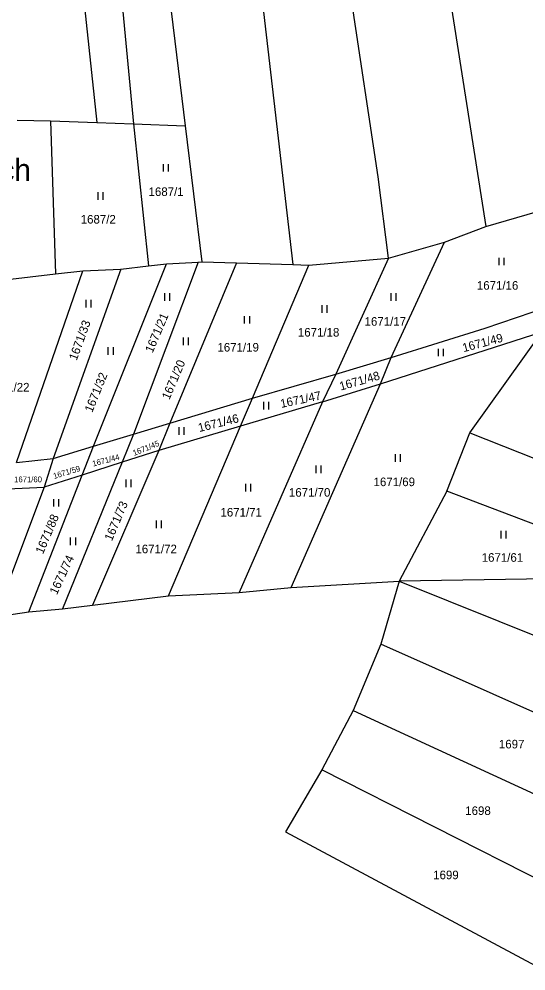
# Model space of a CAD drawing. Extents: x -820420 to -815896, y -1105820 to -1103643.
# Drawn here: x -818858.6 to -818758.1, y -1105776.2 to -1105587.5 of the extents above; entities that cross this region are included whole.
import ezdxf
from ezdxf.enums import TextEntityAlignment as Align

# ---------------------------------------------------------------- set-up
doc = ezdxf.new("R2010")
doc.units = 0
doc.header["$LTSCALE"] = 0.68
for name, color, linetype, lineweight in [('1', 7, 'Continuous', 25), ('3', 7, 'Continuous', 25), ('7', 7, 'Continuous', 13)]:
    doc.layers.add(name, color=color, linetype=linetype, lineweight=lineweight)
doc.layers.add('2', color=7, linetype='Continuous')

msp = doc.modelspace()

# ---------------------------------------------------------------- linework, layer by layer
at = {"layer": '1'}
for p, q in [((-818788.31, -1105486.7), (-818766.07, -1105628.64)), ((-818821.17, -1105491.56), (-818804.3, -1105636.15)), ((-818851.26, -1105531.39), (-818843.19, -1105608.05)), ((-818843.21, -1105531.89), (-818835.93, -1105608.31)), ((-818834.93, -1105532.61), (-818825.68, -1105608.67)), ((-818787.42, -1105618.77), (-818797.13, -1105553.87)), ((-818858.99, -1105607.58), (-818852.36, -1105607.72)), ((-818852.36, -1105607.72), (-818843.19, -1105608.05)), ((-818852.36, -1105607.72), (-818851.38, -1105638.05)), ((-818843.19, -1105608.05), (-818835.93, -1105608.31)), ((-818835.93, -1105608.31), (-818832.96, -1105636.44)), ((-818835.93, -1105608.31), (-818825.68, -1105608.67)), ((-818825.68, -1105608.67), (-818822.37, -1105635.67)), ((-818785.34, -1105634.91), (-818787.42, -1105618.77)), ((-818766.07, -1105628.64), (-818749.42, -1105623.81)), ((-818774.23, -1105631.72), (-818766.07, -1105628.64)), ((-818785.34, -1105634.91), (-818774.23, -1105631.72)), ((-818784.86, -1105654.62), (-818774.23, -1105631.72)), ((-818801.16, -1105636.33), (-818785.34, -1105634.91)), ((-818785.34, -1105634.91), (-818795.81, -1105657.93)), ((-818838.43, -1105637.08), (-818851.81, -1105674.65)), ((-818845.98, -1105637.45), (-818838.43, -1105637.08)), ((-818843.83, -1105672.19), (-818829.35, -1105636.05)), ((-818838.43, -1105637.08), (-818832.96, -1105636.44)), ((-818823.07, -1105635.74), (-818835.89, -1105669.82)), ((-818832.96, -1105636.44), (-818829.35, -1105636.05)), ((-818829.35, -1105636.05), (-818823.07, -1105635.74)), ((-818815.5, -1105635.86), (-818828.73, -1105667.61)), ((-818823.07, -1105635.74), (-818822.37, -1105635.67)), ((-818822.37, -1105635.67), (-818815.5, -1105635.86)), ((-818815.5, -1105635.86), (-818804.3, -1105636.15)), ((-818812.33, -1105662.65), (-818801.16, -1105636.33)), ((-818804.3, -1105636.15), (-818801.16, -1105636.33)), ((-818861.39, -1105639.19), (-818851.38, -1105638.05)), ((-818859.12, -1105675.46), (-818845.98, -1105637.45)), ((-818851.38, -1105638.05), (-818845.98, -1105637.45)), ((-818766.17, -1105648.82), (-818751.84, -1105643.87)), ((-818786.95, -1105659.82), (-818754.88, -1105649.51)), ((-818784.86, -1105654.62), (-818766.17, -1105648.82)), ((-818769.23, -1105669.54), (-818754.88, -1105649.51)), ((-818795.81, -1105657.93), (-818784.86, -1105654.62)), ((-818786.95, -1105659.82), (-818784.86, -1105654.62)), ((-818812.33, -1105662.65), (-818795.81, -1105657.93)), ((-818795.81, -1105657.93), (-818798.43, -1105663.39)), ((-818804.66, -1105700.2), (-818786.95, -1105659.82)), ((-818798.43, -1105663.39), (-818786.95, -1105659.82)), ((-818828.73, -1105667.61), (-818812.33, -1105662.65)), ((-818798.43, -1105663.39), (-818814.95, -1105701.17)), ((-818814.71, -1105668.21), (-818812.33, -1105662.65)), ((-818798.43, -1105663.39), (-818814.71, -1105668.21)), ((-818835.89, -1105669.82), (-818828.73, -1105667.61)), ((-818828.73, -1105667.61), (-818830.91, -1105673.08)), ((-818814.71, -1105668.21), (-818830.91, -1105673.08)), ((-818829, -1105701.85), (-818814.71, -1105668.21)), ((-818843.83, -1105672.19), (-818835.89, -1105669.82)), ((-818835.89, -1105669.82), (-818838.16, -1105675.39)), ((-818851.81, -1105674.65), (-818843.83, -1105672.19)), ((-818846.06, -1105677.91), (-818843.83, -1105672.19)), ((-818830.91, -1105673.08), (-818844.05, -1105703.73)), ((-818830.91, -1105673.08), (-818838.16, -1105675.39)), ((-818859.12, -1105675.46), (-818851.81, -1105674.65)), ((-818851.81, -1105674.65), (-818853.62, -1105680.32)), ((-818838.16, -1105675.39), (-818849.98, -1105704.43)), ((-818838.16, -1105675.39), (-818846.06, -1105677.91)), ((-818856.63, -1105705.05), (-818846.06, -1105677.91)), ((-818846.06, -1105677.91), (-818853.62, -1105680.32)), ((-818853.62, -1105680.32), (-818863.3, -1105706)), ((-818860.91, -1105680.64), (-818853.62, -1105680.32)), ((-818773.82, -1105681.11), (-818783.23, -1105698.96)), ((-818728.85, -1105698.12), (-818773.82, -1105681.11)), ((-818804.66, -1105700.2), (-818783.23, -1105698.96)), ((-818783.23, -1105698.96), (-818786.91, -1105711.43)), ((-818728.85, -1105698.12), (-818783.23, -1105698.96)), ((-818783.23, -1105698.96), (-818725.43, -1105722.12)), ((-818829, -1105701.85), (-818814.95, -1105701.17)), ((-818814.95, -1105701.17), (-818804.66, -1105700.2)), ((-818844.05, -1105703.73), (-818829, -1105701.85)), ((-818863.3, -1105706), (-818856.63, -1105705.05)), ((-818856.63, -1105705.05), (-818849.98, -1105704.43)), ((-818849.98, -1105704.43), (-818844.05, -1105703.73)), ((-818786.91, -1105711.43), (-818792.36, -1105724.6)), ((-818731.23, -1105736.23), (-818786.91, -1105711.43)), ((-818792.36, -1105724.6), (-818798.58, -1105736.34)), ((-818792.36, -1105724.6), (-818740.08, -1105748.69)), ((-818798.58, -1105736.34), (-818805.75, -1105748.63)), ((-818747.45, -1105762.29), (-818798.58, -1105736.34)), ((-818805.75, -1105748.63), (-818754.28, -1105776.22))]:
    msp.add_line(p, q, dxfattribs=at)
msp.add_lwpolyline([(-818773.82, -1105681.11), (-818769.23, -1105669.54), (-818712.97, -1105691.83)], dxfattribs=at)
at = {"layer": '3'}
for p, q in [((-818829.961, -1105617.76), (-818829.961, -1105616.26)), ((-818828.96, -1105617.76), (-818828.96, -1105616.26)), ((-818842.931, -1105623.36), (-818842.931, -1105621.86)), ((-818841.93, -1105623.36), (-818841.93, -1105621.86)), ((-818763.411, -1105636.34), (-818763.411, -1105634.84)), ((-818762.41, -1105636.34), (-818762.41, -1105634.84)), ((-818829.721, -1105643.37), (-818829.721, -1105641.87)), ((-818828.72, -1105643.37), (-818828.72, -1105641.87)), ((-818784.831, -1105643.37), (-818784.831, -1105641.87)), ((-818783.83, -1105643.37), (-818783.83, -1105641.87)), ((-818845.311, -1105644.68), (-818845.311, -1105643.18)), ((-818844.31, -1105644.68), (-818844.31, -1105643.18)), ((-818798.531, -1105645.75), (-818798.531, -1105644.25)), ((-818797.53, -1105645.75), (-818797.53, -1105644.25)), ((-818813.881, -1105647.89), (-818813.881, -1105646.39)), ((-818812.88, -1105647.89), (-818812.88, -1105646.39)), ((-818826.031, -1105652.18), (-818826.031, -1105650.68)), ((-818825.03, -1105652.18), (-818825.03, -1105650.68)), ((-818840.911, -1105654.08), (-818840.911, -1105652.58)), ((-818839.91, -1105654.08), (-818839.91, -1105652.58)), ((-818775.431, -1105654.38), (-818775.431, -1105652.88)), ((-818774.43, -1105654.38), (-818774.43, -1105652.88)), ((-818810.071, -1105664.92), (-818810.071, -1105663.42)), ((-818809.07, -1105664.92), (-818809.07, -1105663.42)), ((-818826.861, -1105669.92), (-818826.861, -1105668.42)), ((-818825.86, -1105669.92), (-818825.86, -1105668.42)), ((-818784.001, -1105675.28), (-818784.001, -1105673.78)), ((-818783, -1105675.28), (-818783, -1105673.78)), ((-818799.721, -1105677.55), (-818799.721, -1105676.05)), ((-818798.72, -1105677.55), (-818798.72, -1105676.05)), ((-818837.381, -1105680.31), (-818837.381, -1105678.81)), ((-818836.38, -1105680.31), (-818836.38, -1105678.81)), ((-818813.651, -1105681.18), (-818813.651, -1105679.68)), ((-818812.65, -1105681.18), (-818812.65, -1105679.68)), ((-818851.731, -1105684.17), (-818851.731, -1105682.67)), ((-818850.73, -1105684.17), (-818850.73, -1105682.67)), ((-818831.341, -1105688.43), (-818831.341, -1105686.93)), ((-818830.34, -1105688.43), (-818830.34, -1105686.93)), ((-818763.051, -1105690.47), (-818763.051, -1105688.97)), ((-818762.05, -1105690.47), (-818762.05, -1105688.97)), ((-818848.371, -1105691.8), (-818848.371, -1105690.3)), ((-818847.37, -1105691.8), (-818847.37, -1105690.3))]:
    msp.add_line(p, q, dxfattribs=at)

# ---------------------------------------------------------------- texts
at = {"layer": '2'}
for s, height, p in [('1687/1', 1.7, (-818829.45, -1105622.595)), ('1687/2', 1.7, (-818842.9, -1105628.065)), ('1671/16', 1.7, (-818763.729, -1105641.175)), ('1671/17', 1.7, (-818785.989, -1105648.315)), ('1671/18', 1.7, (-818799.209, -1105650.465)), ('1671/19', 1.7, (-818815.159, -1105653.435)), ('1671/22', 1.7, (-818860.639, -1105661.355)), ('1671/60', 1.14, (-818856.82, -1105679.345)), ('1671/69', 1.7, (-818784.209, -1105680.115)), ('1671/70', 1.7, (-818800.989, -1105682.205)), ('1671/71', 1.7, (-818814.559, -1105686.135)), ('1671/72', 1.7, (-818831.419, -1105693.415)), ('1671/61', 1.7, (-818762.769, -1105695.105)), ('1697', 1.7, (-818760.94, -1105732.105)), ('1698', 1.7, (-818767.61, -1105745.295)), ('1699', 1.7, (-818773.97, -1105758.035))]:
    msp.add_text(s, height=height, dxfattribs=at).set_placement(p, align=Align.CENTER)
for s, height, rotation, p in [('1671/21', 1.7, 67, (-818830.5266, -1105650.0371)), ('1671/33', 1.7, 70, (-818845.7759, -1105651.4572)), ('1671/49', 1.7, 15, (-818766.488, -1105652.4997)), ('1671/20', 1.7, 67, (-818827.1966, -1105659.3271)), ('1671/32', 1.7, 68, (-818842.5598, -1105661.8264)), ('1671/48', 1.7, 16, (-818790.8728, -1105660.0536)), ('1671/47', 1.7, 12, (-818802.6007, -1105663.7661)), ('1671/46', 1.7, 14, (-818818.8821, -1105668.4058)), ('1671/45', 1.14, 22, (-818833.224, -1105673.0999)), ('1671/44', 1.14, 15, (-818841.2405, -1105675.5349)), ('1671/59', 1.139, 17, (-818849.0015, -1105677.8956)), ('1671/73', 1.7, 67, (-818838.5866, -1105687.3371)), ('1671/88', 1.7, 67, (-818852.2466, -1105689.9171)), ('1671/74', 1.7, 65, (-818849.3696, -1105698.0367))]:
    msp.add_text(s, height=height, rotation=rotation, dxfattribs=at).set_placement(p, align=Align.CENTER)
at = {"layer": '7'}
msp.add_text('V lukách', height=4.4, dxfattribs=at).set_placement((-818867.53, -1105619.65), align=Align.CENTER)

doc.saveas('drawing.dxf')
